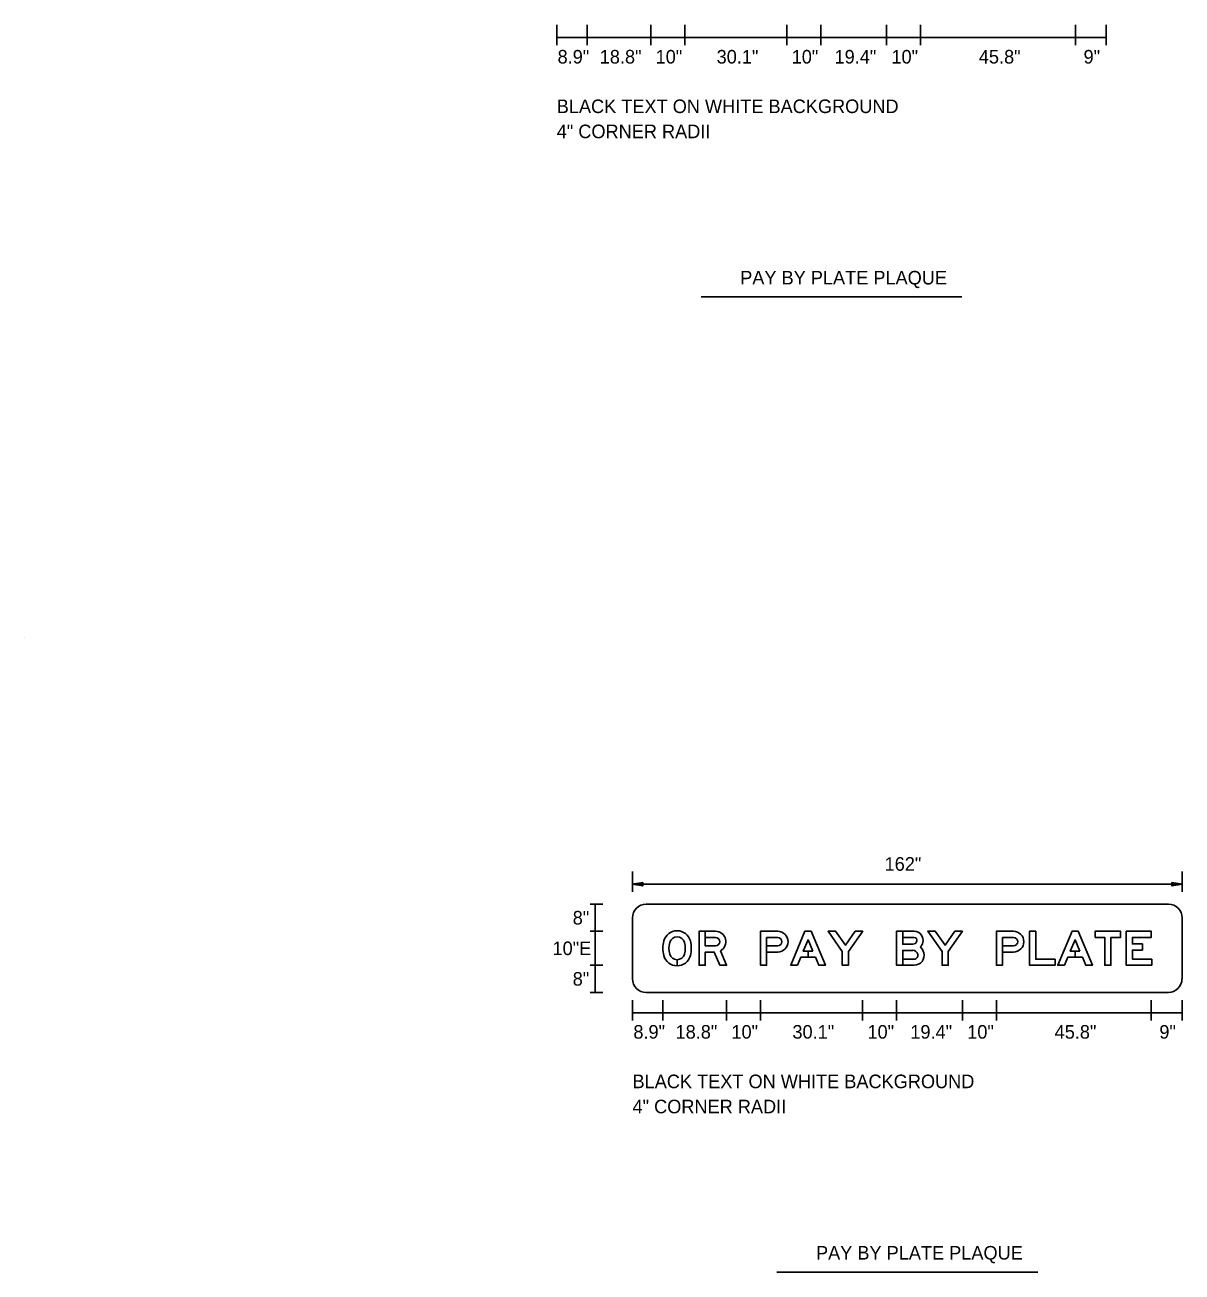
# Model space of a CAD drawing. Extents: x 10268312 to 10268706, y 2142548 to 2142786.
# Drawn here: x 10268312.2 to 10268376.2, y 2142548.2 to 2142617.1 of the extents above; entities that cross this region are included whole.
import ezdxf

# ---------------------------------------------------------------- set-up
doc = ezdxf.new("R2010")
doc.units = 0
for name, color, linetype in [('AdhocPoint_dp', 7, 'Continuous'), ('GSBWFill', 7, 'Continuous'), ('GSColorFill', 7, 'Continuous'), ('GSDims', 7, 'Continuous'), ('GSOutline', 7, 'Continuous'), ('TextLabel', 7, 'Continuous'), ('TextMisc', 7, 'Continuous')]:
    doc.layers.add(name, color=color, linetype=linetype)

msp = doc.modelspace()

# ---------------------------------------------------------------- linework, layer by layer
at = {"layer": 'AdhocPoint_dp'}
msp.add_line((10268312.23, 2142583.281), (10268312.23, 2142583.281), dxfattribs=at)
at = {"layer": 'GSBWFill'}
for p, q in [((10268346.557, 2142568.522), (10268375.425, 2142568.522)), ((10268345.807, 2142564.397), (10268345.807, 2142567.772)), ((10268376.175, 2142567.772), (10268376.175, 2142564.397)), ((10268353.219, 2142566.685), (10268353.828, 2142566.685)), ((10268366.25, 2142566.685), (10268366.859, 2142566.685)), ((10268348.269, 2142565.115), (10268348.269, 2142565.452)), ((10268348.269, 2142565.452), (10268348.269, 2142565.115)), ((10268375.425, 2142563.647), (10268346.557, 2142563.647))]:
    msp.add_line(p, q, dxfattribs=at)
for points in [[(10268350.661, 2142565.945), (10268351.006, 2142565.147), (10268350.638, 2142565.147), (10268350.322, 2142565.879), (10268349.825, 2142565.879), (10268349.825, 2142565.147), (10268349.487, 2142565.147), (10268349.487, 2142567.022), (10268349.825, 2142567.022), (10268349.825, 2142566.216), (10268350.394, 2142566.216)], [(10268349.825, 2142566.685), (10268349.825, 2142567.022), (10268350.394, 2142567.022)], [(10268353.828, 2142567.022), (10268352.881, 2142567.022), (10268352.881, 2142565.147), (10268353.219, 2142565.147), (10268353.219, 2142566.685)], [(10268361.293, 2142566.31), (10268360.737, 2142566.31), (10268360.737, 2142567.022), (10268360.4, 2142567.022), (10268360.4, 2142565.147), (10268360.737, 2142565.147)], [(10268361.366, 2142567.022), (10268360.738, 2142567.022), (10268360.738, 2142566.685), (10268361.366, 2142566.685)], [(10268366.859, 2142567.022), (10268365.912, 2142567.022), (10268365.912, 2142565.147), (10268366.25, 2142565.147), (10268366.25, 2142566.685)], [(10268350.394, 2142566.685), (10268349.825, 2142566.685)], [(10268353.828, 2142566.216), (10268353.219, 2142566.216), (10268353.219, 2142565.879), (10268353.828, 2142565.879)], [(10268360.737, 2142565.147), (10268360.737, 2142565.972), (10268361.293, 2142565.972)], [(10268366.859, 2142566.216), (10268366.25, 2142566.216), (10268366.25, 2142565.879), (10268366.859, 2142565.879)], [(10268361.366, 2142565.485), (10268360.738, 2142565.485), (10268360.738, 2142565.147), (10268361.366, 2142565.147)]]:
    msp.add_lwpolyline(points, dxfattribs=at)
for points in [[(10268355.77, 2142565.926), (10268355.506, 2142565.926), (10268355.506, 2142565.588), (10268355.911, 2142565.588), (10268356.096, 2142565.147), (10268356.462, 2142565.147), (10268355.675, 2142567.022), (10268355.337, 2142567.022), (10268354.55, 2142565.147), (10268354.916, 2142565.147), (10268355.101, 2142565.588), (10268355.506, 2142565.588), (10268355.506, 2142565.926), (10268355.243, 2142565.926), (10268355.506, 2142566.553)], [(10268357.737, 2142565.907), (10268358.525, 2142567.022), (10268358.112, 2142567.022), (10268357.569, 2142566.253), (10268357.026, 2142567.022), (10268356.612, 2142567.022), (10268357.4, 2142565.907), (10268357.4, 2142565.147), (10268357.737, 2142565.147)], [(10268363.25, 2142565.907), (10268364.037, 2142567.022), (10268363.624, 2142567.022), (10268363.081, 2142566.253), (10268362.538, 2142567.022), (10268362.125, 2142567.022), (10268362.912, 2142565.907), (10268362.912, 2142565.147), (10268363.25, 2142565.147)], [(10268369.156, 2142565.147), (10268369.156, 2142565.476), (10268368.088, 2142565.476), (10268368.088, 2142567.022), (10268367.75, 2142567.022), (10268367.75, 2142565.147)], [(10268370.526, 2142565.926), (10268370.263, 2142565.926), (10268370.263, 2142565.588), (10268370.668, 2142565.588), (10268370.853, 2142565.147), (10268371.219, 2142565.147), (10268370.431, 2142567.022), (10268370.094, 2142567.022), (10268369.306, 2142565.147), (10268369.672, 2142565.147), (10268369.857, 2142565.588), (10268370.263, 2142565.588), (10268370.263, 2142565.926), (10268369.999, 2142565.926), (10268370.263, 2142566.553)], [(10268371.369, 2142566.685), (10268371.903, 2142566.685), (10268371.903, 2142565.147), (10268372.241, 2142565.147), (10268372.241, 2142566.685), (10268372.775, 2142566.685), (10268372.775, 2142567.022), (10268371.369, 2142567.022)], [(10268374.5, 2142565.485), (10268373.431, 2142565.485), (10268373.431, 2142565.989), (10268373.984, 2142565.989), (10268373.984, 2142566.327), (10268373.431, 2142566.327), (10268373.431, 2142566.685), (10268374.472, 2142566.685), (10268374.472, 2142567.022), (10268373.094, 2142567.022), (10268373.094, 2142565.147), (10268374.5, 2142565.147)]]:
    msp.add_lwpolyline(points, close=True, dxfattribs=at)
for centre, radius, start, end in [((10268346.557, 2142567.772), 0.75, 90, 180), ((10268375.425, 2142567.772), 0.75, 0, 90), ((10268348.269, 2142566.295), 0.76, 14.96177, 165.03823), ((10268350.394, 2142566.451), 0.572, 297.837, 90), ((10268353.828, 2142566.451), 0.572, 270, 90), ((10268361.366, 2142566.526), 0.497, 345.52249, 90), ((10268366.859, 2142566.451), 0.572, 270, 90), ((10268349.056, 2142566.085), 1.575, 165.03823, 194.96177), ((10268349.056, 2142566.085), 1.238, 165.03823, 194.96177), ((10268348.269, 2142566.295), 0.422, 14.96177, 165.03823), ((10268347.481, 2142566.085), 1.238, 345.03823, 14.96177), ((10268347.481, 2142566.085), 1.575, 345.03823, 14.96177), ((10268350.394, 2142566.451), 0.234, 270, 90), ((10268353.828, 2142566.451), 0.234, 270, 90), ((10268361.293, 2142566.544), 0.234, 270, 345.52249), ((10268361.366, 2142566.526), 0.159, 345.52249, 90), ((10268361.293, 2142566.544), 0.572, 316.7114, 345.52249), ((10268366.859, 2142566.451), 0.234, 270, 90), ((10268348.269, 2142565.875), 0.76, 194.96177, 270), ((10268348.269, 2142565.875), 0.422, 194.96177, 270), ((10268348.269, 2142565.875), 0.422, 270.01272, 345.03823), ((10268348.269, 2142565.875), 0.76, 270.00707, 345.03823), ((10268361.293, 2142565.682), 0.291, 14.47751, 90), ((10268361.366, 2142565.701), 0.553, 270, 14.47751), ((10268361.366, 2142565.701), 0.216, 270, 14.47751), ((10268361.293, 2142565.682), 0.628, 14.47751, 48.4921), ((10268346.557, 2142564.397), 0.75, 180, 270), ((10268375.418, 2142564.397), 0.75, 270, 0)]:
    msp.add_arc(centre, radius, start, end, dxfattribs=at)
at = {"layer": 'GSColorFill'}
for p, q in [((10268353.219, 2142566.685), (10268353.828, 2142566.685)), ((10268366.25, 2142566.685), (10268366.859, 2142566.685)), ((10268348.269, 2142565.115), (10268348.269, 2142565.452)), ((10268348.269, 2142565.452), (10268348.269, 2142565.115))]:
    msp.add_line(p, q, dxfattribs=at)
for points in [[(10268350.661, 2142565.945), (10268351.006, 2142565.147), (10268350.638, 2142565.147), (10268350.322, 2142565.879), (10268349.825, 2142565.879), (10268349.825, 2142565.147), (10268349.487, 2142565.147), (10268349.487, 2142567.022), (10268349.825, 2142567.022), (10268349.825, 2142566.216), (10268350.394, 2142566.216)], [(10268349.825, 2142566.685), (10268349.825, 2142567.022), (10268350.394, 2142567.022)], [(10268353.828, 2142567.022), (10268352.881, 2142567.022), (10268352.881, 2142565.147), (10268353.219, 2142565.147), (10268353.219, 2142566.685)], [(10268361.293, 2142566.31), (10268360.737, 2142566.31), (10268360.737, 2142567.022), (10268360.4, 2142567.022), (10268360.4, 2142565.147), (10268360.737, 2142565.147)], [(10268361.366, 2142567.022), (10268360.738, 2142567.022), (10268360.738, 2142566.685), (10268361.366, 2142566.685)], [(10268366.859, 2142567.022), (10268365.912, 2142567.022), (10268365.912, 2142565.147), (10268366.25, 2142565.147), (10268366.25, 2142566.685)], [(10268350.394, 2142566.685), (10268349.825, 2142566.685)], [(10268353.828, 2142566.216), (10268353.219, 2142566.216), (10268353.219, 2142565.879), (10268353.828, 2142565.879)], [(10268360.737, 2142565.147), (10268360.737, 2142565.972), (10268361.293, 2142565.972)], [(10268366.859, 2142566.216), (10268366.25, 2142566.216), (10268366.25, 2142565.879), (10268366.859, 2142565.879)], [(10268361.366, 2142565.485), (10268360.738, 2142565.485), (10268360.738, 2142565.147), (10268361.366, 2142565.147)]]:
    msp.add_lwpolyline(points, dxfattribs=at)
for points in [[(10268355.77, 2142565.926), (10268355.506, 2142565.926), (10268355.506, 2142565.588), (10268355.911, 2142565.588), (10268356.096, 2142565.147), (10268356.462, 2142565.147), (10268355.675, 2142567.022), (10268355.337, 2142567.022), (10268354.55, 2142565.147), (10268354.916, 2142565.147), (10268355.101, 2142565.588), (10268355.506, 2142565.588), (10268355.506, 2142565.926), (10268355.243, 2142565.926), (10268355.506, 2142566.553)], [(10268357.737, 2142565.907), (10268358.525, 2142567.022), (10268358.112, 2142567.022), (10268357.569, 2142566.253), (10268357.026, 2142567.022), (10268356.612, 2142567.022), (10268357.4, 2142565.907), (10268357.4, 2142565.147), (10268357.737, 2142565.147)], [(10268363.25, 2142565.907), (10268364.037, 2142567.022), (10268363.624, 2142567.022), (10268363.081, 2142566.253), (10268362.538, 2142567.022), (10268362.125, 2142567.022), (10268362.912, 2142565.907), (10268362.912, 2142565.147), (10268363.25, 2142565.147)], [(10268369.156, 2142565.147), (10268369.156, 2142565.476), (10268368.088, 2142565.476), (10268368.088, 2142567.022), (10268367.75, 2142567.022), (10268367.75, 2142565.147)], [(10268370.526, 2142565.926), (10268370.263, 2142565.926), (10268370.263, 2142565.588), (10268370.668, 2142565.588), (10268370.853, 2142565.147), (10268371.219, 2142565.147), (10268370.431, 2142567.022), (10268370.094, 2142567.022), (10268369.306, 2142565.147), (10268369.672, 2142565.147), (10268369.857, 2142565.588), (10268370.263, 2142565.588), (10268370.263, 2142565.926), (10268369.999, 2142565.926), (10268370.263, 2142566.553)], [(10268371.369, 2142566.685), (10268371.903, 2142566.685), (10268371.903, 2142565.147), (10268372.241, 2142565.147), (10268372.241, 2142566.685), (10268372.775, 2142566.685), (10268372.775, 2142567.022), (10268371.369, 2142567.022)], [(10268374.5, 2142565.485), (10268373.431, 2142565.485), (10268373.431, 2142565.989), (10268373.984, 2142565.989), (10268373.984, 2142566.327), (10268373.431, 2142566.327), (10268373.431, 2142566.685), (10268374.472, 2142566.685), (10268374.472, 2142567.022), (10268373.094, 2142567.022), (10268373.094, 2142565.147), (10268374.5, 2142565.147)]]:
    msp.add_lwpolyline(points, close=True, dxfattribs=at)
for centre, radius, start, end in [((10268348.269, 2142566.295), 0.76, 14.96177, 165.03823), ((10268350.394, 2142566.451), 0.572, 297.837, 90), ((10268353.828, 2142566.451), 0.572, 270, 90), ((10268361.366, 2142566.526), 0.497, 345.52249, 90), ((10268366.859, 2142566.451), 0.572, 270, 90), ((10268349.056, 2142566.085), 1.575, 165.03823, 194.96177), ((10268349.056, 2142566.085), 1.238, 165.03823, 194.96177), ((10268348.269, 2142566.295), 0.422, 14.96177, 165.03823), ((10268347.481, 2142566.085), 1.238, 345.03823, 14.96177), ((10268347.481, 2142566.085), 1.575, 345.03823, 14.96177), ((10268350.394, 2142566.451), 0.234, 270, 90), ((10268353.828, 2142566.451), 0.234, 270, 90), ((10268361.293, 2142566.544), 0.234, 270, 345.52249), ((10268361.366, 2142566.526), 0.159, 345.52249, 90), ((10268361.293, 2142566.544), 0.572, 316.7114, 345.52249), ((10268366.859, 2142566.451), 0.234, 270, 90), ((10268348.269, 2142565.875), 0.76, 194.96177, 270), ((10268348.269, 2142565.875), 0.422, 194.96177, 270), ((10268348.269, 2142565.875), 0.422, 270.01272, 345.03823), ((10268348.269, 2142565.875), 0.76, 270.00707, 345.03823), ((10268361.293, 2142565.682), 0.291, 14.47751, 90), ((10268361.366, 2142565.701), 0.553, 270, 14.47751), ((10268361.366, 2142565.701), 0.216, 270, 14.47751), ((10268361.293, 2142565.682), 0.628, 14.47751, 48.4921)]:
    msp.add_arc(centre, radius, start, end, dxfattribs=at)
at = {"layer": 'GSDims'}
for p, q in [((10268341.618, 2142617.093), (10268341.618, 2142615.968)), ((10268343.294, 2142617.093), (10268343.294, 2142615.968)), ((10268346.818, 2142617.093), (10268346.818, 2142615.968)), ((10268348.693, 2142617.093), (10268348.693, 2142615.968)), ((10268354.336, 2142617.093), (10268354.336, 2142615.968)), ((10268356.212, 2142617.093), (10268356.212, 2142615.968)), ((10268359.849, 2142617.093), (10268359.849, 2142615.968)), ((10268361.724, 2142617.093), (10268361.724, 2142615.968)), ((10268370.284, 2142617.093), (10268370.284, 2142615.968)), ((10268371.986, 2142617.093), (10268371.986, 2142615.968)), ((10268341.618, 2142616.39), (10268343.294, 2142616.39)), ((10268343.294, 2142616.39), (10268346.818, 2142616.39)), ((10268346.818, 2142616.39), (10268348.693, 2142616.39)), ((10268348.693, 2142616.39), (10268354.336, 2142616.39)), ((10268354.336, 2142616.39), (10268356.212, 2142616.39)), ((10268356.212, 2142616.39), (10268359.849, 2142616.39)), ((10268359.849, 2142616.39), (10268361.724, 2142616.39)), ((10268361.724, 2142616.39), (10268370.284, 2142616.39)), ((10268370.284, 2142616.39), (10268371.986, 2142616.39)), ((10268349.596, 2142602.067), (10268364.009, 2142602.067)), ((10268345.807, 2142569.203), (10268345.807, 2142570.328)), ((10268376.175, 2142569.203), (10268376.175, 2142570.328)), ((10268345.807, 2142569.625), (10268376.175, 2142569.625)), ((10268344.165, 2142568.522), (10268343.462, 2142568.522)), ((10268343.743, 2142568.522), (10268343.743, 2142567.022)), ((10268344.165, 2142567.022), (10268343.462, 2142567.022)), ((10268343.743, 2142565.147), (10268343.743, 2142567.022)), ((10268344.165, 2142565.147), (10268343.462, 2142565.147)), ((10268343.743, 2142565.147), (10268343.743, 2142563.647)), ((10268344.165, 2142563.647), (10268343.462, 2142563.647)), ((10268345.807, 2142563.226), (10268345.807, 2142562.101)), ((10268347.482, 2142563.226), (10268347.482, 2142562.101)), ((10268351.006, 2142563.226), (10268351.006, 2142562.101)), ((10268352.881, 2142563.226), (10268352.881, 2142562.101)), ((10268358.524, 2142563.226), (10268358.524, 2142562.101)), ((10268360.4, 2142563.226), (10268360.4, 2142562.101)), ((10268364.037, 2142563.226), (10268364.037, 2142562.101)), ((10268365.912, 2142563.226), (10268365.912, 2142562.101)), ((10268374.472, 2142563.226), (10268374.472, 2142562.101)), ((10268376.175, 2142563.226), (10268376.175, 2142562.101)), ((10268345.807, 2142562.522), (10268347.482, 2142562.522)), ((10268347.482, 2142562.522), (10268351.006, 2142562.522)), ((10268351.006, 2142562.522), (10268352.881, 2142562.522)), ((10268352.881, 2142562.522), (10268358.524, 2142562.522)), ((10268358.524, 2142562.522), (10268360.4, 2142562.522)), ((10268360.4, 2142562.522), (10268364.037, 2142562.522)), ((10268364.037, 2142562.522), (10268365.912, 2142562.522)), ((10268365.912, 2142562.522), (10268374.472, 2142562.522)), ((10268374.472, 2142562.522), (10268376.175, 2142562.522)), ((10268353.784, 2142548.2), (10268368.197, 2142548.2))]:
    msp.add_line(p, q, dxfattribs=at)
for points in [[(10268345.807, 2142569.625), (10268346.369, 2142569.531), (10268346.369, 2142569.718)], [(10268376.175, 2142569.625), (10268375.612, 2142569.531), (10268375.612, 2142569.718)]]:
    msp.add_lwpolyline(points, close=True, dxfattribs=at)
at = {"layer": 'GSOutline'}
for p, q in [((10268353.219, 2142566.685), (10268353.828, 2142566.685)), ((10268366.25, 2142566.685), (10268366.859, 2142566.685)), ((10268353.219, 2142565.879), (10268353.828, 2142565.879)), ((10268366.25, 2142565.879), (10268366.859, 2142565.879)), ((10268360.4, 2142565.147), (10268361.366, 2142565.147))]:
    msp.add_line(p, q, dxfattribs=at)
for points in [[(10268350.394, 2142567.022), (10268349.487, 2142567.022), (10268349.487, 2142565.147), (10268349.825, 2142565.147), (10268349.825, 2142565.879), (10268350.322, 2142565.879), (10268350.638, 2142565.147), (10268351.006, 2142565.147), (10268350.661, 2142565.945)], [(10268353.828, 2142567.022), (10268352.881, 2142567.022), (10268352.881, 2142565.147), (10268353.219, 2142565.147), (10268353.219, 2142565.879)], [(10268361.366, 2142567.022), (10268360.4, 2142567.022), (10268360.4, 2142565.147)], [(10268366.859, 2142567.022), (10268365.912, 2142567.022), (10268365.912, 2142565.147), (10268366.25, 2142565.147), (10268366.25, 2142565.879)], [(10268350.394, 2142566.685), (10268349.825, 2142566.685), (10268349.825, 2142566.216), (10268350.394, 2142566.216)], [(10268353.828, 2142566.216), (10268353.219, 2142566.216), (10268353.219, 2142566.685)], [(10268361.293, 2142566.31), (10268360.737, 2142566.31), (10268360.737, 2142566.685), (10268361.366, 2142566.685)], [(10268366.859, 2142566.216), (10268366.25, 2142566.216), (10268366.25, 2142566.685)], [(10268361.293, 2142565.972), (10268360.737, 2142565.972), (10268360.737, 2142565.485), (10268361.366, 2142565.485)]]:
    msp.add_lwpolyline(points, dxfattribs=at)
for points in [[(10268355.101, 2142565.588), (10268355.911, 2142565.588), (10268356.096, 2142565.147), (10268356.462, 2142565.147), (10268355.675, 2142567.022), (10268355.337, 2142567.022), (10268354.55, 2142565.147), (10268354.916, 2142565.147)], [(10268357.737, 2142565.907), (10268358.525, 2142567.022), (10268358.112, 2142567.022), (10268357.569, 2142566.253), (10268357.026, 2142567.022), (10268356.612, 2142567.022), (10268357.4, 2142565.907), (10268357.4, 2142565.147), (10268357.737, 2142565.147)], [(10268363.25, 2142565.907), (10268364.037, 2142567.022), (10268363.624, 2142567.022), (10268363.081, 2142566.253), (10268362.538, 2142567.022), (10268362.125, 2142567.022), (10268362.912, 2142565.907), (10268362.912, 2142565.147), (10268363.25, 2142565.147)], [(10268369.156, 2142565.147), (10268369.156, 2142565.476), (10268368.088, 2142565.476), (10268368.088, 2142567.022), (10268367.75, 2142567.022), (10268367.75, 2142565.147)], [(10268369.857, 2142565.588), (10268370.668, 2142565.588), (10268370.853, 2142565.147), (10268371.219, 2142565.147), (10268370.431, 2142567.022), (10268370.094, 2142567.022), (10268369.306, 2142565.147), (10268369.672, 2142565.147)], [(10268371.369, 2142566.685), (10268371.903, 2142566.685), (10268371.903, 2142565.147), (10268372.241, 2142565.147), (10268372.241, 2142566.685), (10268372.775, 2142566.685), (10268372.775, 2142567.022), (10268371.369, 2142567.022)], [(10268374.5, 2142565.485), (10268373.431, 2142565.485), (10268373.431, 2142565.989), (10268373.984, 2142565.989), (10268373.984, 2142566.327), (10268373.431, 2142566.327), (10268373.431, 2142566.685), (10268374.472, 2142566.685), (10268374.472, 2142567.022), (10268373.094, 2142567.022), (10268373.094, 2142565.147), (10268374.5, 2142565.147)], [(10268355.77, 2142565.926), (10268355.506, 2142566.553), (10268355.243, 2142565.926)], [(10268370.526, 2142565.926), (10268370.263, 2142566.553), (10268369.999, 2142565.926)]]:
    msp.add_lwpolyline(points, close=True, dxfattribs=at)
for centre, radius, start, end in [((10268348.269, 2142566.295), 0.76, 14.96177, 165.03823), ((10268350.394, 2142566.451), 0.572, 297.837, 90), ((10268353.828, 2142566.451), 0.572, 270, 90), ((10268361.366, 2142566.526), 0.497, 345.52249, 90), ((10268366.859, 2142566.451), 0.572, 270, 90), ((10268349.056, 2142566.085), 1.575, 165.03823, 194.96177), ((10268349.056, 2142566.085), 1.238, 165.03823, 194.96177), ((10268348.269, 2142566.295), 0.422, 14.96177, 165.03823), ((10268347.481, 2142566.085), 1.238, 345.03823, 14.96177), ((10268347.481, 2142566.085), 1.575, 345.03823, 14.96177), ((10268350.394, 2142566.451), 0.234, 270, 90), ((10268353.828, 2142566.451), 0.234, 270, 90), ((10268361.293, 2142566.544), 0.234, 270, 345.52249), ((10268361.366, 2142566.526), 0.159, 345.52249, 90), ((10268361.293, 2142566.544), 0.572, 316.7114, 345.52249), ((10268366.859, 2142566.451), 0.234, 270, 90), ((10268348.269, 2142565.875), 0.76, 194.96177, 345.03823), ((10268348.269, 2142565.875), 0.422, 194.96177, 345.03823), ((10268361.293, 2142565.682), 0.291, 14.47751, 90), ((10268361.366, 2142565.701), 0.553, 270, 14.47751), ((10268361.366, 2142565.701), 0.216, 270, 14.47751), ((10268361.293, 2142565.682), 0.628, 14.47751, 48.4921)]:
    msp.add_arc(centre, radius, start, end, dxfattribs=at)

# ---------------------------------------------------------------- texts
at = {"layer": 'GSDims'}
for s, p in [('8.9"', (10268341.665, 2142614.961)), ('18.8"', (10268343.995, 2142614.961)), ('10"', (10268347.082, 2142614.961)), ('30.1"', (10268350.454, 2142614.961)), ('10"', (10268354.601, 2142614.961)), ('19.4"', (10268356.97, 2142614.961)), ('10"', (10268360.114, 2142614.961)), ('45.8"', (10268364.943, 2142614.961)), ('9"', (10268370.731, 2142614.961)), ('162"', (10268359.737, 2142570.369)), ('8"', (10268342.5, 2142567.397)), ('10"E', (10268341.384, 2142565.71)), ('8"', (10268342.5, 2142564.022)), ('8.9"', (10268345.853, 2142561.094)), ('18.8"', (10268348.184, 2142561.094)), ('10"', (10268351.271, 2142561.094)), ('30.1"', (10268354.642, 2142561.094)), ('10"', (10268358.789, 2142561.094)), ('19.4"', (10268361.158, 2142561.094)), ('10"', (10268364.302, 2142561.094)), ('45.8"', (10268369.132, 2142561.094)), ('9"', (10268374.92, 2142561.094))]:
    msp.add_text(s, height=0.75, dxfattribs=at).set_placement(p)
at = {"layer": 'TextLabel'}
for p in [(10268351.757, 2142602.756), (10268355.946, 2142548.889)]:
    msp.add_text('PAY BY PLATE PLAQUE', height=0.75, dxfattribs=at).set_placement(p)
at = {"layer": 'TextMisc'}
for s, p in [('BLACK TEXT ON WHITE BACKGROUND', (10268341.618, 2142612.224)), ('4" CORNER RADII', (10268341.618, 2142610.836)), ('BLACK TEXT ON WHITE BACKGROUND', (10268345.807, 2142558.357)), ('4" CORNER RADII', (10268345.807, 2142556.969))]:
    msp.add_text(s, height=0.75, dxfattribs=at).set_placement(p)

doc.saveas('drawing.dxf')
